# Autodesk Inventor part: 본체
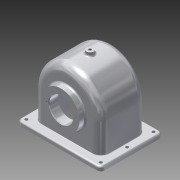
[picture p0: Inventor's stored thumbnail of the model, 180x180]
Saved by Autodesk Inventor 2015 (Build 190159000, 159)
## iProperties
Created: 2015-09
Part Number: 본체
Material: 알루미늄 6061
Document SubType Name: Modeling
Designer: PHO-02
Mass: 706.03 g
Surface Area: 933.855 cm^2
Volume: 261.493 cm^3
Density: 2.7 g/cm^3
Appearance: 알루미늄 - 평지
Author: PHO-02
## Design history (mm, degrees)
sketch "스케치1"
  geometry: L1 (56, 0)-(56, -47); L2 (56, -47)-(-56, -47); L3 (-56, -47)-(-56, 0); 2 further points; 1 other entity
  constraints: 6 end point, 1 coincident, 1 parallel, 4 other
extrude "돌출1" new body sketch "스케치1" stored distance "d4" = 77; taper "d5" = 0 deg
sketch "스케치2"
  geometry: C1 r 31 at (0, 0); 1 further point
  constraints: 1 centre point, 1 coincident
  dimensions: "d6" = 62 diameter of C1
extrude "돌출2" join sketch "스케치2" distance "d7" = 10; taper "d8" = 0 deg
node "작업 평면1"
sketch "스케치4"
  geometry: C1 r 6 at (0, 0); 1 further point
  constraints: 1 centre point, 1 coincident
  dimensions: "d14" = 12 diameter of C1
extrude "돌출3" join sketch "스케치4" distance "d15" = 20; taper "d16" = 0 deg
sketch "스케치5"
  geometry: L1 (56, -38.5)-(56, -90.5); L2 (56, -90.5)-(-14, -90.5); L3 (-14, -90.5)-(126, -90.5); L4 (126, -90.5)-(126, 13.5); L5 (126, 13.5)-(-14, 13.5); L6 (-14, 13.5)-(-14, -90.5)
  constraints: 12 end point, 2 parallel, 2 perpendicular, 1 horizontal, 1 vertical
  dimensions: "d17" = 52 distance of L1.start L1.end; "d18" = 70 distance of L1.end L2.end; "d19" = 140 distance of L5.end L4.end; "d20" = 104 distance of L4.end L3.end
extrude "돌출4" join sketch "스케치5" distance "d21" = 7; taper "d22" = 0 deg
sketch "스케치6"
  geometry: L1 (126, -90.5)-(126, 13.5) reference; L2 (126, 13.5)-(126, 5.5); L3 (126, 5.5)-(118, 5.5); L4 (118, 5.5)-(118, -38.5); L5 (118, -38.5)-(118, -82.5); C1 r 2.5 at (118, 5.5); C2 r 2.5 at (118, -38.5); C3 r 2.5 at (118, -82.5); 1 further point
  constraints: 8 end point, 3 centre point, 3 coincident, 2 vertical, 1 perpendicular, 1 point on line
  dimensions: "d23" = 8 distance of L1.end L2.end; "d24" = 8 distance of L2.end L3.end; "d25" = 5 diameter of C1; "d26" = 44 distance of L4.start L4.end; "d27" = 5 diameter of C2; "d28" = 44 distance of L5.start L5.end; "d29" = 5 diameter of C3
extrude "돌출5" cut sketch "스케치6" distance "d30" = 7; taper "d31" = 0 deg
sketch "스케치7"
  geometry: C1 r 20 at (0, 0); 1 further point
  constraints: 1 centre point, 1 coincident
  dimensions: "d32" = 40 diameter of C1
extrude "돌출6" cut sketch "스케치7" distance "d33" = 15; taper "d34" = 0 deg
sketch "스케치8"
  geometry: L1 (-56, -47)-(-56, 0) reference; L2 (56, 0)-(56, -47) reference; L3 (-51, -54)-(-51, 0); L4 (51, 0)-(51, -54); L5 (-70, -54)-(70, -54) reference; 2 further points; 1 other entity
  constraints: 4 end point, 2 point on line, 1 horizontal alignment, 3 other
  dimensions: "d35" = 5 distance between parallel lines of L3 L1
extrude "돌출7" cut sketch "스케치8" stored distance "d36" = 67; taper "d37" = 0 deg
sketch "스케치10"
  geometry: L1 (0, -33.5)-(-54, -33.5) reference; L2 (0, -33.5)-(0, -19.5); L3 (0, 33.5)-(0, -33.5) reference; L4 (0, -19.5)-(28, -19.5); L5 (28, -19.5)-(41.446, -35.525); L6 (0, -33.5)-(39.747, -33.5); 1 further point
  constraints: 8 end point, 2 point on line, 1 horizontal, 1 perpendicular
  dimensions: "d41" = 14 distance of L1.start L2.end; "d42" = 28 distance of L2.end L4.end; "d43" = 130 deg angle of L4 L5
revolve "회전1" sketch "스케치10" stored, may be unused: angle "d44" = 90 deg
sketch "스케치11"
  geometry: L1 (0, -38.5)-(57, -38.5) reference; L2 (-33, -35.5)-(-33, -34.5); L3 (-33, -34.5)-(-40.979, -44.009); L4 (-33, -35.5)-(0, -35.5); L5 (0, -35.5)-(0, -38.5); L6 (0, -38.5)-(-36.356, -38.5); L7 (0, -38.5)-(-47, -38.5) reference; 1 further point
  constraints: 10 end point, 2 point on line, 1 horizontal, 1 perpendicular, 1 vertical
  dimensions: "d47" = 1 distance of L2.start L2.end; "d49" = 33 distance of L2.start L4.end
revolve "회전2" sketch "스케치11" stored, may be unused: angle "d50" = 90 deg
sketch "스케치12"
  geometry: L1 (0, 0)-(0, 28); 1 further point
  constraints: 2 end point, 1 coincident, 1 vertical
  dimensions: "d51" = 28 distance of L1.start L1.end
hole "구멍1" sketch "스케치12" at (0, 28) diameter "d52" = 2.459; stored, may be unused: countersink angle "d56" = 90 deg, drill point angle "d58" = 118 deg; dims "d53" = 7, "d54" = 4, "d55" = 2, "d57" = 9
sketch "스케치13"
  geometry: 2 further points
  constraints: 1 coincident
hole "구멍2" sketch "스케치13" at (0, 0) diameter "d62" = 4.134; stored, may be unused: countersink angle "d66" = 90 deg, drill point angle "d68" = 118 deg; dims "d63" = 10, "d64" = 4, "d65" = 2, "d67" = 14.2
sketch "스케치14"
  geometry: L1 (0, 0)-(0, 24); 1 further point
  constraints: 2 end point, 1 coincident, 1 vertical
  dimensions: "d69" = 24 distance of L1.start L1.end
hole "구멍3" sketch "스케치14" at (0, 24) diameter "d70" = 2.459; stored, may be unused: countersink angle "d74" = 90 deg, drill point angle "d76" = 118 deg; dims "d71" = 6, "d72" = 4, "d73" = 2, "d75" = 8.8
chamfer "모따기1" distance "d80" = 1; stored, may be unused: second distance "d81" = 2, angle "d82" = 45 deg
sketch "스케치15"
  geometry: C1 r 20 at (0, 0); 1 further point
  constraints: 1 centre point, 1 coincident
  dimensions: "d83" = 40 diameter of C1
extrude "돌출9" cut sketch "스케치15" stored distance "d84" = 3; taper "d85" = 0 deg
chamfer "모따기2" distance "d86" = 1; stored, may be unused: second distance "d87" = 2, angle "d88" = 45 deg
fillet "모깎기1" dims "d89" = 0.5
fillet "모깎기2" dims "d90" = 7
fillet "모깎기3" dims "d91" = 14
fillet "모깎기4" dims "d92" = 9
fillet "모깎기5" dims "d93" = 1
fillet "모깎기6" dims "d94" = 3
sketch "스케치16"
  geometry: L1 (-14, 0)-(-14, -46) reference; L2 (69.5, -47)-(-20.5, -47) reference; L3 (-14, -44.148)-(-14, -47); L4 (-14, -47)-(24.5, -47); L5 (24.5, -47)-(24.5, -17); 3 further points
  constraints: 6 end point, 2 coincident, 2 point on line, 2 vertical, 1 midpoint, 1 other
  dimensions: "d95" = 38.5 distance of L3.end L4.end; "d96" = 30 distance of L4.end L5.end
feature "엠보싱2" sketch "스케치16" dims "d17" = 52, "d18" = 70, "d19" = 140, "d20" = 104, "d97" = 0.5, "d98" = 0
node "솔리드1"
mirror "대칭1"
pattern_circular "원형 패턴1" dims angle "d60" = 360 deg
pattern_circular "원형 패턴2" dims angle "d78" = 360 deg
other parameters: "d13" = 63
